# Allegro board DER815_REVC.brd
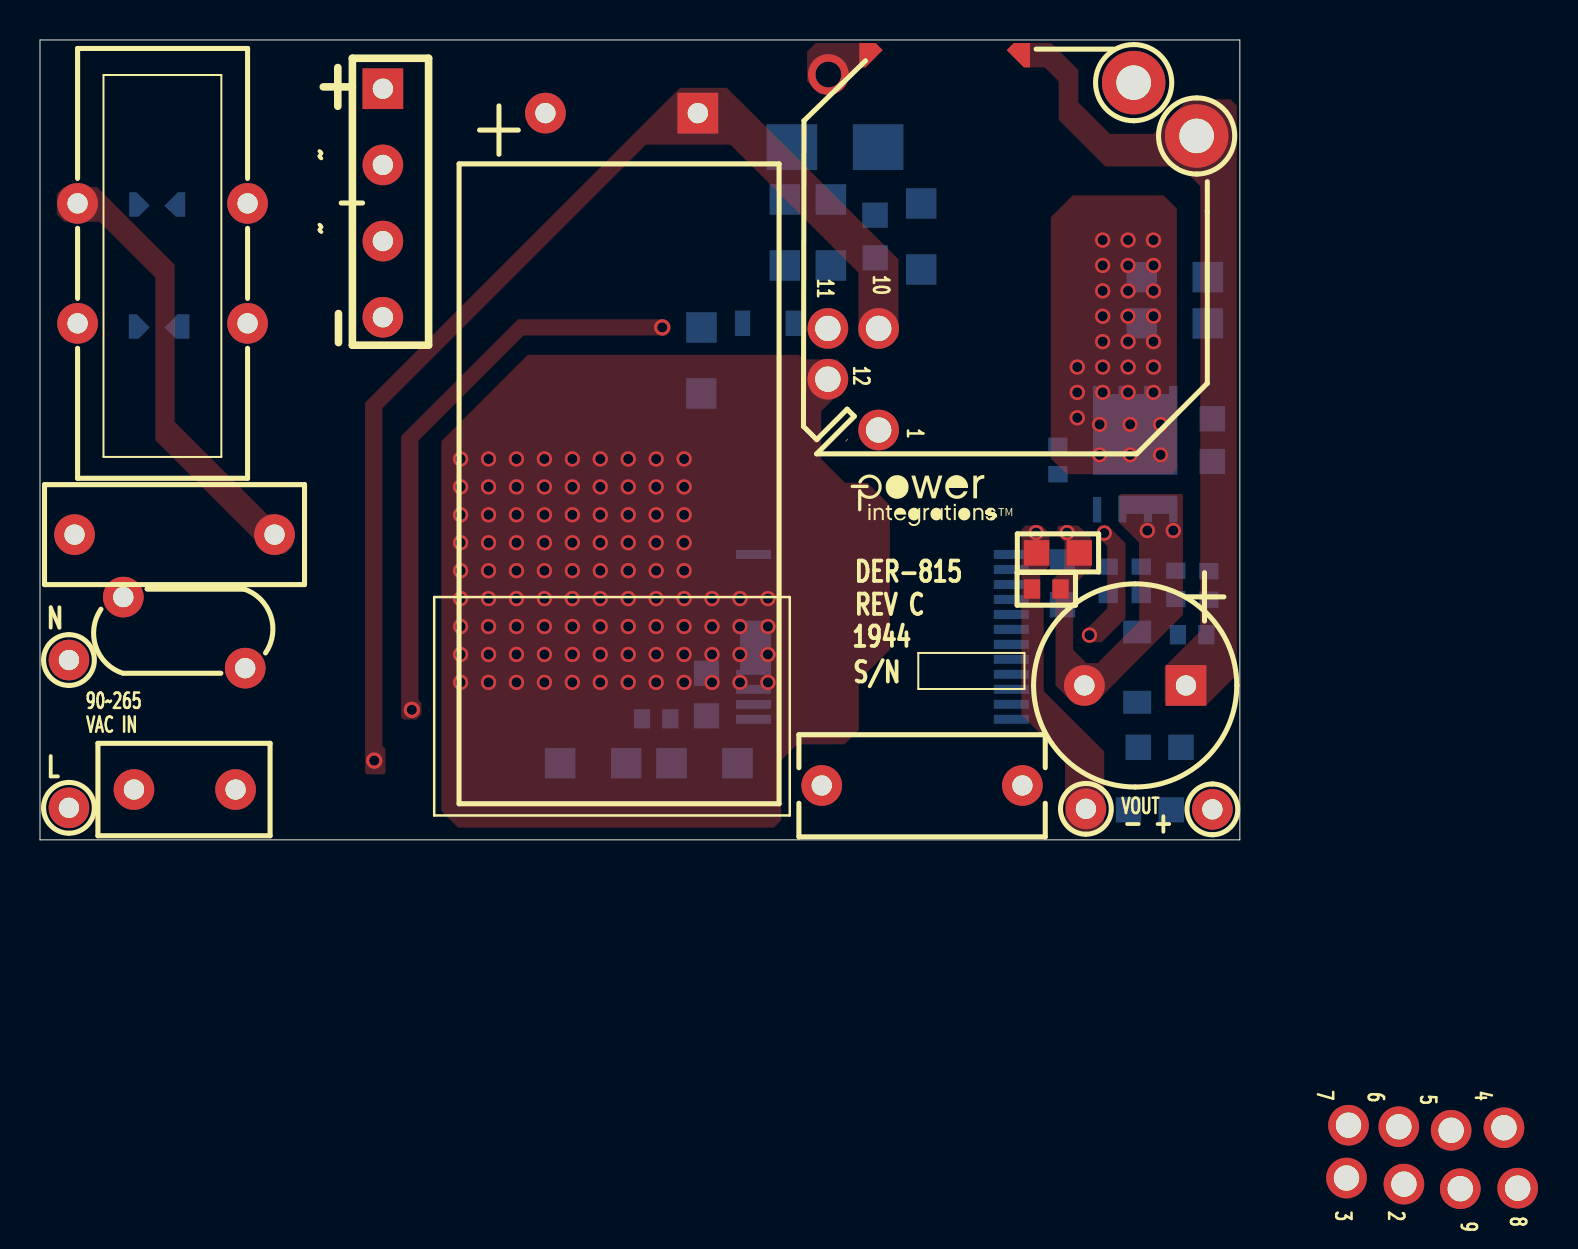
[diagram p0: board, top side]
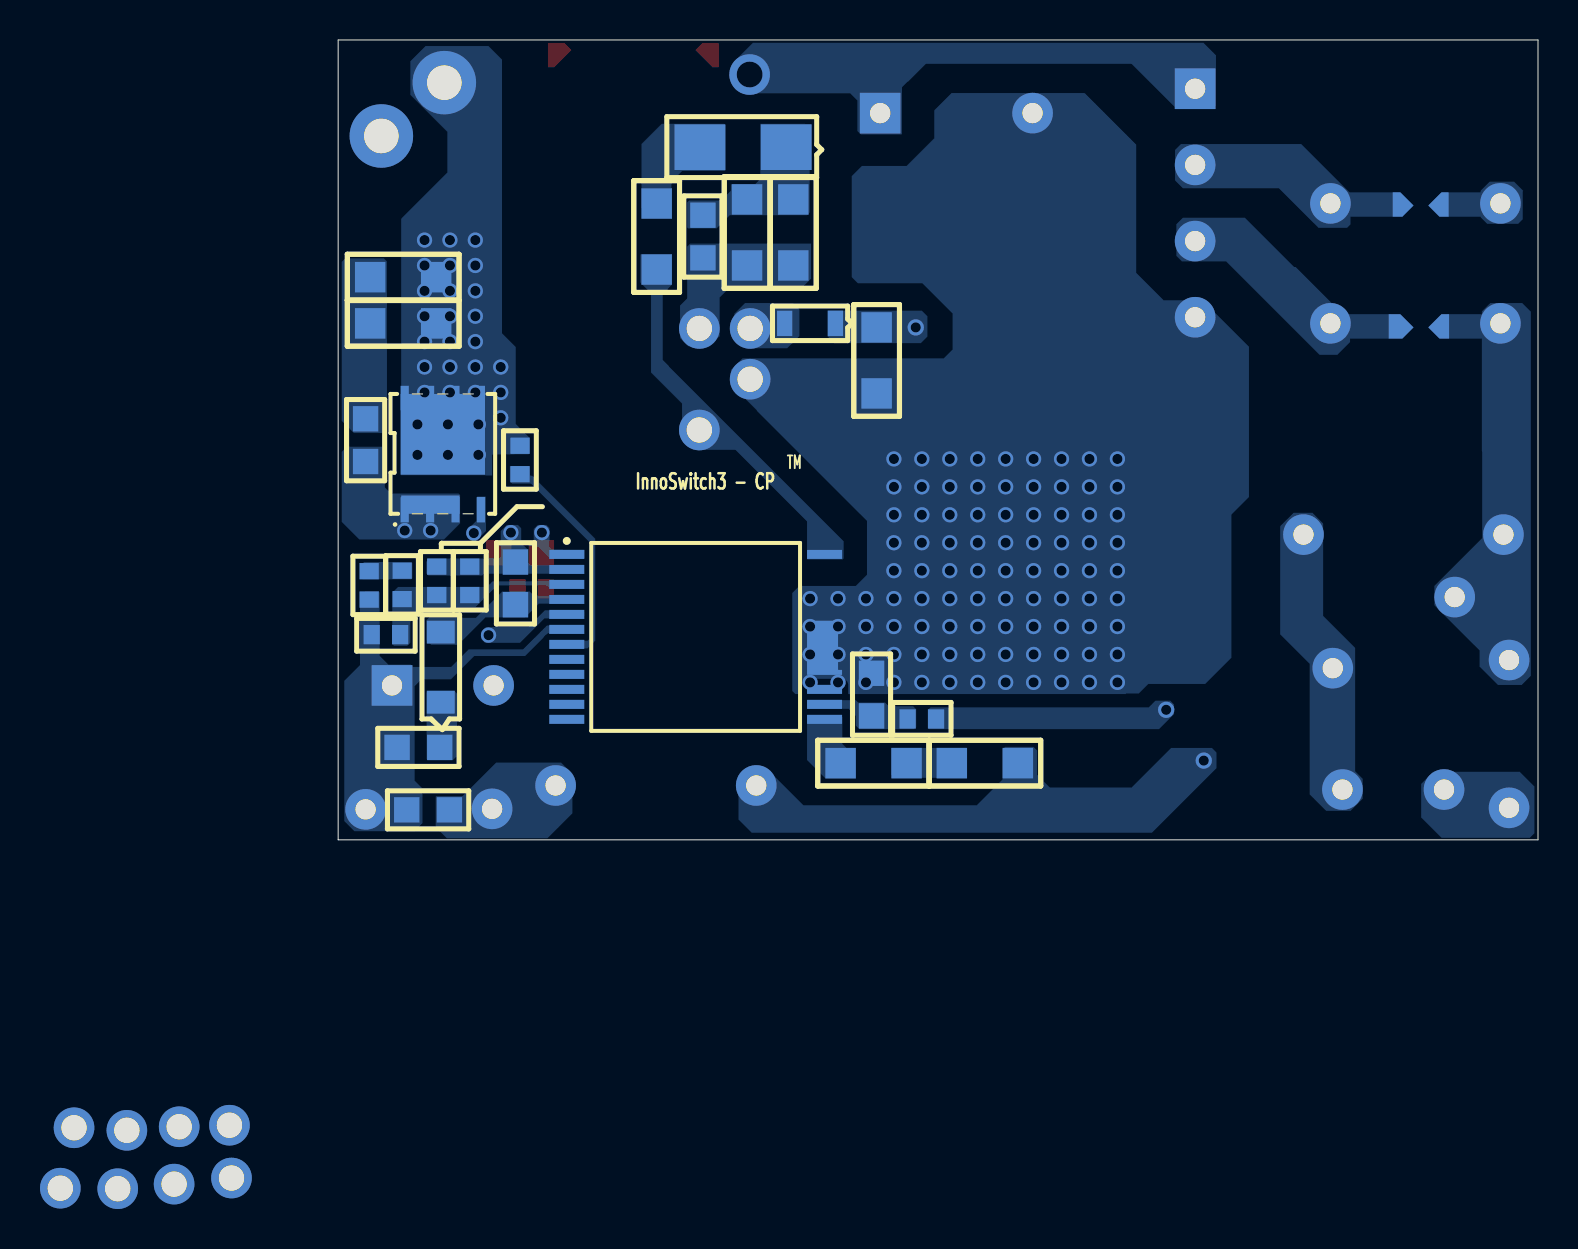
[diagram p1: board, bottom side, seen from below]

Outline 59.99 x 40.01 mm; copper layers: TOP, BOTTOM. Coordinates in mm from the lower left corner of the outline.
Outline path: 0,40.01 0,0 59.99,0 59.99,40.01 0,40.01

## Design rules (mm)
constraint set DEFAULT: min track width 0.508

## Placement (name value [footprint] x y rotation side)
BR1  UD4KB100-BP  [PIDAXBRIDGED3K]  17.14 37.57 270 top
C1  0.1 uF  [PINPXCAPRAD5X13X11P1MM040]  1.73 15.27 0 top
C2  4700 pF  [PISMC0805]  41.76 29.11 90 bottom
C3  100 uF  [PIPOLCAPCLYD630LS300040]  25.27 36.35 0 top
C4  22 uf  [PISMC1206]  33.07 25.63 270 bottom
C5  4.7 uF  [PISMC0805]  33.32 6.2 90 bottom
C6  2.2 nF  [PI_NP475X200LS395D040]  39.09 2.72 0 top
C7  2.2 nF  [PISMC0805]  58.62 21.06 270 bottom
C8  2.2 uF  [PISMC0805]  51.13 11.76 90 bottom
C9  470 uF  [PIPOLCAPCYLD400LS200040]  57.3 7.72 180 top
C11  0.033 uF  [PISMC0603]  56.79 13.46 270 bottom
C12  10 uF  [PISMC0805]  56.57 1.5 180 bottom
C13  2.2 nF  [PISMC0603]  55.07 12.24 90 bottom
D1  S1K  [PISMDO214AC12]  37.59 34.65 0 bottom
D2  BAV21WS-7-F  [PISMSOD323]  35.13 25.83 0 bottom
F1  2 A  [PI_RST_MICROFUSE]  4.7 2.51 0 top
FL1  Hole_90  [PI_HOLE_70MIL]  57.84 35.18 0 top
FL2  Hole_90  [PI_HOLE_70MIL]  54.69 37.85 0 top
L1  22 mH  [PI_IND_4P_21P5X11MMD041]  1.88 25.83 0 top
NOREF  -  []  39.98 18.16 0 top
NOREF#2  -  []  -228.6 -144.78 0 top
NOREF#3  -  []  60 0 90 top
NOREF#4  -  []  -150.78 54.23 0 top
NOREF#5  -  []  0 40 0 top
Q1  AONS62922  [PISMPQFN5X6B]  56.67 16.51 180 bottom
R3  402 k  [PISMR1206]  39.55 28.73 90 bottom
R4  4.7  [PISMR1206]  44.07 31.83 270 bottom
R6  30 k  [PISMR0603]  30.1 6.05 0 bottom
R7  17.4  [PISMR1206]  58.39 28.14 180 bottom
R8  17.4  [PISMR1206]  58.39 25.83 180 bottom
R9  47  [PISMR0603]  50.9 19.71 270 bottom
R10  0.012  [PISMR0805]  51.97 14.35 180 top
R12  287 k  [PISMR0603]  58.32 10.26 180 bottom
R13  15.8 k  [PISMR0603]  53.42 12.24 90 bottom
R14  100 k  [PISMR0603]  58.45 12.01 90 bottom
R15  1.91 M  [PISMR1206]  31.57 3.84 0 bottom
R16  1.91 M  [PISMR1206]  26.01 3.84 0 bottom
R17  1  [PISMR0603]  51.03 12.55 180 top
R18  402 k  [PISMR1206]  37.24 28.73 90 bottom
R19  750  [PISMR0805]  54.91 4.62 0 bottom
RV1  275 Vac  [PIDISC350X160LS210X140040]  4.17 12.14 0 top
T1  RM8  [PI_BOBBIN_RM8_12P_ENERTRONIC]  41.94 20.5 270 top
TP1  L  [PITPKEYSTONE100X100]  1.45 8.99 0 top
TP2  N  [PITPKEYSTONE100X100]  1.45 1.6 0 top
TP10  -V  [PITPKEYSTONE100X100]  52.3 1.55 0 top
TP11  +V  [PITPKEYSTONE100X100]  58.62 1.52 0 top
U2  INN3268C-H221  [PI_IC_INSOP_24D]  48.56 14.27 180 bottom
VR1  MMSZ5250B-7-F  [PI_SM_SOD-123_12]  54.86 6.88 90 bottom

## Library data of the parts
BR1 = DISCRETE BRIDGE_+~~-: alternate symbols: (pidaxbridgeD3K_horz)
C1 = CAP NP: alternate symbols: (pinpxcaprad5x13x11p1mm040h)
C2 C4-C8 C13 = CAP NP
C3 = CAP POL: alternate symbols: (pipolcapclyd630ls3000401260h)
C9 = CAP POL: alternate symbols: (pipolcapcyld400ls200040800h)
C11 = CAP NP: alternate symbols: (pismc0603_1)
C12 = CAP NP: alternate symbols: (pismc0805_1)
D1 D2 = DIODE
F1 = FUSE: alternate symbols: (pirstmicrofusehoz)
FL1 FL2 = FlyingLead
L1 = INDUCTOR_4P_revB
Q1 = FET_N_SGD_123_4_5678
R3 R4 R6-R10 R12-R19 = R
RV1 = VARISTOR: alternate symbols: (pi_disc_354x220_ls220x10_040_h)
T1 = BRM8_12P/GENERIC_1: alternate symbols: (pi_bobbin_rm8_12p_clp)
TP1 TP2 TP10 TP11 = TESTPOINT
U2 = Inno3CP
VR1 = DIODE_ZENER

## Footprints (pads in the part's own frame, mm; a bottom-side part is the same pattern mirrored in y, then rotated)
PI_BOBBIN_RM8_12P_ENERTRONIC
  round 2.032 hole 1.27: 1(0,0) 2(37.719,26.264) 3(37.414,23.393) 4(34.9,31.267) 5(35.027,28.626) 6(34.849,26.01) 7(34.773,23.495) 8(37.922,31.953) 9(37.948,29.083) 10(-5.08,0) 11(-5.08,-2.54) 12(-2.54,-2.54)
PI_HOLE_70MIL
  round 3.175 hole 1.727: 1(0,0.025)
PI_IC_INSOP_24D
  rect 1.75x0.45 smd: 1(0,0) 2(0,-0.75) 3(0,-1.5) 4(0,-2.25) 5(0,-3) 6(0,-3.75) 7(0,-4.5) 8(0,-5.25) 9(0,-6) 10(0,-6.75) 11(0,-7.5) 12(0,-8.25) 13(12.89,-8.25) 14(12.89,-7.5) 15(12.89,-6.75) 24(12.89,0)
  custom 0.438x0.438 smd: 16(12.89,-4.67)
PI_IND_4P_21P5X11MMD041
  round 2.032 hole 1.016: 1(0,0) 2(8.5,0) 3(0,6) 4(8.5,6)
PI_NP475X200LS395D040
  round 2.032 hole 1.016: 1(0,0) 2(10.033,0)
PI_RST_MICROFUSE
  round 2.032 hole 1.016: 1(0,0) 2(5.08,0)
PI_SM_SOD-123_12
  rect 1.143x1.397 smd: 1(0,0) 2(3.505,0)
PIDAXBRIDGED3K
  rect 2.032x2.032 hole 1.016: 1(0,0)
  round 2.032 hole 1.016: 2(3.81,0) 3(7.62,0) 4(11.43,0)
PIDISC350X160LS210X140040
  round 2.032 hole 1.016: 1(0,0) 2(6.096,-3.556)
PINPXCAPRAD5X13X11P1MM040
  round 2.032 hole 1.016: 1(0,0) 2(10,0)
PIPOLCAPCLYD630LS300040
  rect 2.032x2.032 hole 1.016: 1(7.62,0)
  round 2.032 hole 1.016: 2(0,0)
PIPOLCAPCYLD400LS200040
  rect 2.032x2.032 hole 1.016: 1(0,0)
  round 2.032 hole 1.016: 2(5.08,0)
PISMC0603
  rect 0.813x0.965 smd: 1(0,0) 2(1.422,0)
PISMC0805
  rect 1.27x1.27 smd: 1(0,0) 2(2.134,0)
PISMC1206
  rect 1.524x1.524 smd: 1(0,0) 2(3.302,0)
PISMDO214AC12
  rect 2.54x2.286 smd: 1(0,0) 2(4.318,0)
PISMPQFN5X6B
  rect 0.406x1.27 smd: 1(0,0) 2(1.27,0) 3(2.54,0) 4(3.81,0)
  rect 0.406x1.219 smd: 5(3.81,5.588) 6(2.54,5.588) 7(1.27,5.588) 8(0,5.588)
PISMR0603
  rect 0.813x0.965 smd: 1(0,0) 2(1.422,0)
PISMR0805
  rect 1.27x1.27 smd: 1(0,0) 2(2.134,0)
PISMR1206
  rect 1.524x1.524 smd: 1(0,0) 2(3.302,0)
PISMSOD323
  rect 0.762x1.27 smd: 1(0,0) 2(2.54,0)
PITPKEYSTONE100X100
  round 2.032 hole 1.016: 1(0,0)

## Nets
NC8: U2.8
NC9: U2.9
NC10: U2.10
NC11: U2.11
NC12: U2.12
NC15: U2.15
N11266868: BR1.1 C2.1 C3.1 C6.1 R3.1 R16.1 R18.1 T1.10
N11266916: C9.1 C12.1 FL1.1 R12.1 R14.1 R19.2 TP11.1 U2.6
N11267038: C2.2 D1.1 R3.2 R18.2
N11267062: C11.1 R14.2
N11267102: FL2.1 Q1.5 Q1.6 Q1.7 Q1.8 R7.2 R8.2 R9.1
N11267110: C7.1 R7.1 R8.1
N11267188: C11.2 C13.1 R12.2 R13.1 U2.3
N11267230: C6.2 C12.2 R10.2 R17.2 TP10.1 U2.1
N11267290: C7.2 C8.2 C9.2 C13.2 Q1.1 Q1.2 Q1.3(S3) R10.1 R13.2 R17.1 U2.2
N11267634: BR1.2 L1.4
N11267730: BR1.4 C3.2 C4.2 C5.2 T1.12 U2.16
N11267828: C1.2 F1.2 L1.3 RV1.2
N11267852: R9.2 U2.7
N11267958: C8.1 U2.4 VR1.2
N11268086: C5.1 R6.2 U2.14
N11268620: F1.1 TP2.1
N11268626: C1.1 L1.1 RV1.1 TP1.1
N11270541: BR1.3(AC2) L1.2
N11272042: R4.2 T1.1 U2.24
N11272779: D2.2 T1.11
N11273620: C4.1 D2.1 R6.1
N11285778: Q1.4 U2.5
N11293604: R15.1 R16.2
N11293623: R15.2 U2.13(VPIN)
N11314206: D1.2 R4.1
N11323484: R19.1 VR1.1

Pads without a net: T1 2 3 4 5 6 7 8 9

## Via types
v1: diameter 0.762, hole 0.508, TOP to BOTTOM, 129 vias
v2: diameter 0.813, hole 0.508, TOP to BOTTOM, 3 vias
v3: diameter 2.032, hole 1.295, TOP to BOTTOM, 1 via

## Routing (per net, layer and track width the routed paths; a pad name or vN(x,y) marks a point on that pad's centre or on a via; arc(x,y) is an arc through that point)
N11266868:
  vias: v2(16.71,3.96) v3(39.42,38.28)
N11267102:
  vias: v1(51.87,23.65) v1(51.87,22.38) v1(51.87,21.11) v1(52.98,20.78) v1(52.98,19.25) v1(53.14,30) v1(53.14,28.73) v1(53.14,27.46) v1(53.14,26.19) v1(53.14,24.92) v1(53.14,23.65) v1(53.14,22.38) v1(54.41,30) v1(54.41,28.73) v1(54.41,27.46) v1(54.41,26.19) v1(54.41,24.92) v1(54.41,23.65) v1(54.41,22.38) v1(54.51,20.78) v1(54.51,19.25) v1(55.68,30) v1(55.68,28.73) v1(55.68,27.46) v1(55.68,26.19) v1(55.68,24.92) v1(55.68,23.65) v1(55.68,22.38) v1(56.03,20.78) v1(56.03,19.25)
N11267230:
  vias: v1(49.81,15.37)
N11267290:
  vias: v1(51.36,15.37) v1(55.37,15.47) v1(56.67,15.47)
N11267730:
  vias: v1(21.03,19.05) v1(21.03,17.65) v1(21.03,16.26) v1(21.03,14.86) v1(21.03,13.46) v1(21.03,12.06) v1(21.03,10.67) v1(21.03,9.27) v1(21.03,7.87) v1(22.43,19.05) v1(22.43,17.65) v1(22.43,16.26) v1(22.43,14.86) v1(22.43,13.46) v1(22.43,12.06) v1(22.43,10.67) v1(22.43,9.27) v1(22.43,7.87) v1(23.83,19.05) v1(23.83,17.65) v1(23.83,16.26) v1(23.83,14.86) v1(23.83,13.46) v1(23.83,12.06) v1(23.83,10.67) v1(23.83,9.27) v1(23.83,7.87) v1(25.22,19.05) v1(25.22,17.65) v1(25.22,16.26) v1(25.22,14.86) v1(25.22,13.46) v1(25.22,12.06) v1(25.22,10.67) v1(25.22,9.27) v1(25.22,7.87) v1(26.62,19.05) v1(26.62,17.65) v1(26.62,16.26) v1(26.62,14.86) v1(26.62,13.46) v1(26.62,12.06) v1(26.62,10.67) v1(26.62,9.27) v1(26.62,7.87) v1(28.02,19.05) v1(28.02,17.65) v1(28.02,16.26) v1(28.02,14.86) v1(28.02,13.46) v1(28.02,12.06) v1(28.02,10.67) v1(28.02,9.27) v1(28.02,7.87) v1(29.41,19.05) v1(29.41,17.65) v1(29.41,16.26) v1(29.41,14.86) v1(29.41,13.46) v1(29.41,12.06) v1(29.41,10.67) v1(29.41,9.27) v1(29.41,7.87) v1(30.81,19.05) v1(30.81,17.65) v1(30.81,16.26) v1(30.81,14.86) v1(30.81,13.46) v1(30.81,12.06) v1(30.81,10.67) v1(30.81,9.27) v1(30.81,7.87) v1(32.21,19.05) v1(32.21,17.65) v1(32.21,16.26) v1(32.21,14.86) v1(32.21,13.46) v1(32.21,12.06) v1(32.21,10.67) v1(32.21,9.27) v1(32.21,7.87) v1(33.6,12.06) v1(33.6,10.67) v1(33.6,9.27) v1(33.6,7.87) v1(35,12.06) v1(35,10.67) v1(35,9.27) v1(35,7.87) v1(36.4,12.06) v1(36.4,10.67) v1(36.4,9.27) v1(36.4,7.87)
N11273620:
  vias: v2(18.59,6.5) v2(31.11,25.63)
N11285778:
  vias: v1(52.48,10.24) v1(53.21,15.34)

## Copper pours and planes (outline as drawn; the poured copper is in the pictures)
N11266868 on TOP (solid shape): 42.14,39.5 41.27,38.63 40.97,38.63 40.97,39.85 41.78,39.85
N11266868 on TOP: 42.93,29.03 42.93,25.17 42.47,24.71 41.4,24.71 40.92,25.2 40.92,28.37 34.52,34.77 30.3,34.77 17.12,21.59 17.12,4.7 17.27,4.55 17.27,3.35 17.2,3.28 16.33,3.28 16.26,3.35 16.26,21.87 32,37.62 34.34,37.62
N11266868 on TOP: 38.79,39.85 41.07,39.85 41.07,38.63 40.89,38.63 39.57,37.31 38.99,37.31 38.35,37.95 38.35,39.42
N11266868 on BOTTOM: 33.86,35.28 31.83,35.28 31.8,35.31 31.8,37.64 31.52,37.92 31.5,37.92 30.61,38.81 20.32,38.81 18.14,36.63 16.18,36.63 16.1,36.7 16.1,39.24 16.73,39.87 39.26,39.87 39.98,39.14 39.98,37.69 39.62,37.34 34.39,37.34 34.04,36.98 34.04,35.46
N11266868 on BOTTOM: 40.92,25.17 40.92,27.13 40.59,27.46 36.96,27.46 36.35,28.07 36.35,29.82 42.39,29.82 42.55,29.67 42.55,27.08 42.9,26.72 42.9,25.1 42.49,24.69 41.43,24.69 40.94,25.17
N11266868 on BOTTOM: 16.31,4.6 18.34,4.6 20.32,2.62 24.41,2.62 25.04,3.25 25.04,4.47 25.22,4.65 26.64,4.65 26.77,4.52 26.77,3.02 28.04,1.75 28.04,1.73 36.73,1.73 38.56,3.56 39.62,3.56 39.98,3.2 39.98,1.02 39.32,0.36 19.3,0.36 16.08,3.58 16.08,4.37
N11266916 on TOP (solid shape): 49.5,38.63 49.2,38.63 48.34,39.5 48.69,39.85 49.5,39.85
N11266916 on TOP: 49.35,39.85 50.57,39.85 51.92,38.51 51.92,36.88 53.49,35.31 55.68,35.31 57.4,37.03 59.54,37.03 59.84,36.73 59.84,8.26 58.32,6.73 56.41,6.73 56.24,6.91 56.24,8.66 58.01,10.44 58.01,32.69 57.02,33.68 53.26,33.68 50.94,36 50.94,37.93 50.24,38.63 49.35,38.63
N11266916 on BOTTOM: 59.69,0.94 59.18,0.43 56.18,0.43 55.78,0.84 55.78,2.57 56.17,2.96 56.17,7.68 55.83,8.03 54.36,8.03 53.19,9.19 50.65,9.19 49.5,10.34 47.93,10.34 47.8,10.46 47.8,10.62 47.9,10.72 49.56,10.72 50.75,9.53 53.47,9.53 54.34,8.65 56.25,8.65 56.36,8.76 57.48,8.76 57.92,9.21 57.92,12.38 57.99,12.45 58.65,12.45 58.9,12.19 58.9,8.74 59.69,7.95
N11267038 on BOTTOM: 36.42,35.59 36.65,35.81 38.89,35.81 38.89,33.05 39.14,32.79 40.36,32.79 40.36,32.46 40.84,31.98 42.44,31.98 42.55,31.88 42.55,30.63 42.49,30.58 41.07,30.58 40.41,31.24 36.55,31.24 36.42,31.37
N11267062 on BOTTOM: 56.34,13.89 58.7,13.89 58.78,13.82 58.78,13.03 56.34,13.03 56.29,13.08 56.29,13.84
N11267102 on BOTTOM (solid shape): 56.87,18.26 52.65,18.26 52.65,22.3 56.87,22.3
N11267102 on TOP: 56.85,18.52 56.85,31.57 56.18,32.23 51.64,32.23 50.55,31.14 50.55,19.08 51.33,18.29 56.62,18.29
N11267102 on BOTTOM: 52.48,39.7 55.63,39.7 56.39,38.94 56.39,37.26 54.53,35.41 54.53,33.38 56.85,31.06 56.85,18.24 52.63,18.24 52.62,18.22 52.3,18.22 52.3,19.25 52.27,19.28 51.19,19.28 51.19,19.29 50.46,19.29 50.41,19.34 50.41,20.1 51.12,20.8 51.12,24.65 51.8,25.34 51.8,39.03
N11267110 on BOTTOM: 57.56,20.47 57.56,28.93 57.71,29.08 59.64,29.08 59.82,28.91 59.82,20.95 59.21,20.35 57.76,20.35 57.63,20.47
N11267188 on BOTTOM: 48.44,12.93 52.27,12.93 52.55,12.65 57,12.65 57.29,12.36 57.29,9.82 57.3,9.8 57.2,9.7 56.54,9.7 56.39,9.86 56.39,10.9 55.65,11.63 53.14,11.63 52.04,12.73 49.58,12.73 49.43,12.57 48.41,12.57 48.31,12.67 48.31,12.8
N11267230 on TOP: 50.01,13.23 50.01,11.76 50.19,11.58 50.19,7.44 53.21,4.42 53.21,0.88 52.73,0.39 51.8,0.39 51.26,0.94 51.26,4.06 49.07,6.25 49.07,15.52 49.28,15.72 50.09,15.72 50.47,15.34 50.47,13.67 50.44,13.67
N11267230 on BOTTOM: 52.1,3.86 53.77,2.18 55.09,2.18 55.12,2.16 55.12,0.64 54.56,0.08 49.53,0.08 48.29,1.32 48.29,3.3 48.84,3.86
N11267230 on BOTTOM: 47.68,14.1 47.68,14.5 48.74,14.5 48.76,14.52 49.31,14.52 49.43,14.63 49.43,15.6 49.58,15.75 50.01,15.75 50.22,15.54 50.22,14.86 49.43,14.07 47.7,14.07
N11267290 on BOTTOM (solid shape): 56.85,16.31 53.92,16.31 53.92,17.22 56.85,17.22
N11267290 on TOP: 54.24,8.34 54.24,8.33 53.89,7.98 53.89,7.98 52.7,6.78 51.71,6.78 50.78,7.72 50.78,12.02 50.65,12.15 50.65,13.03 51.23,13.61 51.23,14.9 50.86,15.27 50.86,15.63 50.95,15.72 51.92,15.72 52.55,15.09 52.55,13.61 52.11,13.18 52.11,13.16 51.82,12.86 51.82,12.85 51.66,12.7 51.66,9.5 52.32,8.84 52.88,8.84 54.97,10.92 54.97,13.34 54.95,13.35 54.95,14.87 53.98,15.85 53.98,17.22 54.05,17.3 57.1,17.3 57.15,17.25 57.15,11.25
N11267290 on BOTTOM: 47.8,13.74 50.37,13.74 50.52,13.89 50.52,14.53 50.84,14.85 50.84,15.59 51,15.75 51.56,15.75 51.87,15.44 51.87,14.15 51.94,14.07 55.42,14.07 55.59,13.91 55.59,13.32 55.49,13.22 52.79,13.22 52.7,13.31 47.83,13.31 47.75,13.39 47.75,13.69
N11267290 on BOTTOM: 53.9,17.25 53.98,17.32 57.35,17.32 57.66,17.63 57.66,19.26 57.66,19.27 57.66,19.56 57.76,19.66 59.56,19.66 59.82,19.41 59.82,15.9 58.94,15.02 54.7,15.02 53.9,15.82
N11267634 on BOTTOM (solid shape): 7.26,31.17 6.78,31.17 6.22,31.72 6.88,32.38 7.26,32.38
N11267634 on BOTTOM: 7.16,31.17 9.75,31.17 9.8,31.22 9.8,32.31 9.68,32.44 9.6,32.44 9.55,32.38 7.16,32.38
N11267634 on BOTTOM: 9.37,32.33 11.84,34.8 17.86,34.8 18.15,34.51 18.15,32.98 17.75,32.59 12.95,32.59 10.97,30.61 9.55,30.61 9.37,30.78
N11267730 on TOP: 42.49,9.5 40.94,7.95 40.94,5.49 40.23,4.78 37.87,4.78 37.06,3.96 37.06,0.97 36.7,0.61 20.9,0.61 20.07,1.45 20.07,19.94 24.38,24.26 37.95,24.26 38.18,24.03 39.85,24.03 40.31,23.57 40.31,22.68 39.07,21.44 39.07,19.05 40.26,17.86 41.38,17.86 42.49,16.74
N11267730 on BOTTOM: 15.33,9.11 15.33,16.27 14.45,17.15 14.45,24.66 16.78,26.99 18.72,26.99 20.09,28.36 20.09,34.77 22.67,37.35 29.32,37.35 30.19,36.49 30.19,35.09 31.57,33.71 33.81,33.71 34.32,33.2 34.32,28.14 34.01,27.84 30.78,27.84 29.27,26.33 29.27,24.52 29.72,24.08 39.78,24.08 40.36,23.5 40.36,22.78 39.07,21.49 39.07,21.46 33.55,15.95 33.55,13.26 34.11,12.7 36.93,12.7 37.29,12.34 37.29,7.44 37.13,7.29 20.62,7.29 20.6,7.32 19.96,7.32 19.48,7.8 16.64,7.8
N11267828 on BOTTOM (solid shape): 5.49,31.72 4.93,31.17 4.47,31.17 4.47,32.38 4.83,32.38
N11267828 on TOP: 6.73,28.77 6.73,20.9 11.35,16.28 11.81,16.28 12.61,15.48 12.61,14.67 12.27,14.33 11.43,14.33 5.77,19.99 5.77,28.12 2.97,30.91 1.22,30.91 0.84,31.29 0.84,32.31 1.18,32.65 2.84,32.65
N11267828 on BOTTOM: 1.19,32.92 2.41,32.92 2.87,32.46 2.87,31.14 2.54,30.81 0.99,30.81 0.76,31.04 0.76,32.44 0.74,32.46
N11267828 on BOTTOM: 9.14,9.6 10.74,11.2 10.74,15.82 11.28,16.36 12.22,16.36 12.89,15.68 12.89,10.27 11.42,8.8 11.42,2.27 10.59,1.45 9.37,1.45 8.76,2.06 8.76,3.05 9.14,3.43
N11267828 on BOTTOM: 4.55,32.38 1.91,32.38 1.91,31.14 1.93,31.17 4.55,31.17
N11267852 on BOTTOM: 49.35,9.58 47.52,9.58 47.14,9.96 47.14,15.06 50.29,18.21 50.37,18.21 50.42,18.26 50.42,18.64 50.47,18.69 51.41,18.69 51.41,17.93 51.3,17.82 50.36,17.82 47.37,14.83 47.37,10.11 47.52,9.96 49.38,9.96 49.38,9.65 49.35,9.63 49.38,9.6
N11267958 on BOTTOM: 48.56,12.22 50.22,12.22 50.42,12.42 51.79,12.42 53.11,11.1 55.47,11.1 55.58,11 55.58,9.98 55.35,9.75 54,9.75 52.63,11.13 50.65,11.13 49.96,11.81 47.98,11.81 47.73,12.06 47.73,12.12 47.75,12.14 47.75,12.24 48.54,12.24
N11268086 on BOTTOM: 36.5,6.99 36.53,6.96 36.53,6.6 36.47,6.55 34.47,6.55 34.11,6.2 34.11,5.71 33.93,5.54 31.19,5.54 31.09,5.64 31.09,6.53 31.24,6.68 32.46,6.68 32.65,6.87 34,6.87 34.11,6.99
N11268620 on BOTTOM: 4.83,0.1 0.41,0.1 0.18,0.33 0.18,2.67 0.91,3.4 5.23,3.4 5.84,2.79 5.84,1.12
N11268626 on BOTTOM (solid shape): 5.49,25.63 4.93,25.07 4.45,25.07 4.45,26.29 4.83,26.29
N11268626 on BOTTOM: 4.55,26.29 1.91,26.29 1.91,25.04 1.93,25.07 4.55,25.07
N11268626 on BOTTOM: 2.81,19.44 2.79,19.43 2.79,15.09 5.18,12.7 5.18,11.73 2.92,9.47 2.92,8.66 2.01,7.75 0.81,7.75 0.36,8.2 0.36,26.42 0.79,26.85 2.39,26.85 2.81,26.43
N11270541 on BOTTOM (solid shape): 7.47,25.07 6.78,25.07 6.22,25.63 6.88,26.29 7.47,26.29
N11270541 on BOTTOM: 7.37,25.07 9.8,25.07 9.8,26.21 9.73,26.29 7.37,26.29
N11270541 on BOTTOM: 9.4,25.93 12.12,28.65 12.19,28.65 14.66,31.11 17.75,31.11 18.08,30.78 18.08,29.21 17.81,28.93 15.6,28.93 10.92,24.26 10.03,24.26 9.4,24.89
N11272042 on BOTTOM: 43.46,23.67 43.46,23.7 43.76,24 43.76,27.3 43.31,27.76 43.31,29.26 43.33,29.29 44.88,29.29 44.88,27.86 44.35,27.33 44.35,23.37 42.8,21.82 42.8,20.09 42.21,19.51 40.13,19.51 36.55,15.93 36.55,14.05 36.53,14.02 34.77,14.02 34.72,14.07 34.72,14.94
N11272779 on BOTTOM: 37.26,26.85 39.65,26.85 40.18,26.31 40.18,25.17 39.6,24.59 37.54,24.59 36.93,25.2 36.93,26.52
N11273620 on TOP: 31.24,26.04 31.47,25.81 31.47,25.4 31.29,25.22 24.18,25.22 18.92,19.96 18.92,6.99 19.08,6.83 19.08,6.27 18.82,6.02 18.16,6.02 18.06,6.12 18.06,20.19 23.9,26.04
N11273620 on BOTTOM: 30.81,26.47 35.53,26.47 35.53,25.2 35.18,24.84 30.86,24.84 30.53,25.17 30.53,26.19
N11273620 on BOTTOM: 18.2,6.29 18.2,6.77 18.39,6.96 19.13,6.96 19.46,6.62 30.38,6.62 30.49,6.51 30.49,5.58 30.45,5.54 18.95,5.54
N11285778 on TOP: 53.37,14.68 52.86,15.19 52.86,15.54 53.04,15.72 53.39,15.72 54.28,14.83 54.28,11.07 53.09,9.88 52.37,9.88 52.2,10.06 52.2,10.41 53.37,11.58
N11285778 on BOTTOM: 52.6,17.14 52.63,17.17 53.04,17.17 53.09,17.12 53.09,15.95 53.56,15.48 53.56,15.15 53.38,14.97 53.07,14.97 52.6,15.44
N11285778 on BOTTOM: 47.78,11.48 49.66,11.48 50.5,10.64 52.6,10.64 52.83,10.41 52.83,10.03 52.65,9.86 50.9,9.86 49.68,11.07 47.83,11.07 47.7,11.2 47.7,11.4
N11293604 on BOTTOM: 28.6,4.6 32.33,4.6 32.33,3.28 32.16,3.1 28.55,3.1 28.6,3.15
N11293623 on BOTTOM: 34.11,4.57 34.56,4.57 34.79,4.8 34.79,6.13 34.87,6.22 36.5,6.22 36.55,6.17 36.55,3.99 35.62,3.06 34.12,3.06 34.11,3.07
N11314206 on BOTTOM: 43.33,31.7 43.33,32.92 42.8,33.45 40.67,33.45 40.61,33.5 40.61,35.74 40.69,35.81 43.81,35.81 44.83,34.8 44.83,31.62 43.41,31.62
N11323484 on BOTTOM: 54.15,7.42 55.52,7.42 55.58,7.37 55.58,4.04 55.52,3.99 54.25,3.99 54.05,4.19 54.05,7.32

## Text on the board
Ref Des/Silkscreen Bottom: TM | InnoSwitch3 - CP
Ref Des/Silkscreen Top: 90~265 | VAC IN | VOUT | N | L | 1944 | S/N | DER-815 | REV C | - +
User.6: NOTE: PLEASE DELETE THESE PINS | 14.  FAB HOUSE LOGO,DATE CODE TO BE IN SILK SCREEN ONLY.DO NOT USE COPPER. | 13.  MATERIAL FR4 DOUBLE SIDED COPPER 2oz THICKNESS 0.039"
User.8: FIGURE | FINISHED_SIZE | 20.0 | 40.0 | 50.0 | 51.0 | 68.0 | DRILL CHART: TOP to BOTTOM | ALL UNITS ARE IN MILS | TOLERANCE_DRILL | +0.0/-0.0 | +3.0/-3.0 | PLATED | QTY | 129 | 3 | 12 | 1 | 2
